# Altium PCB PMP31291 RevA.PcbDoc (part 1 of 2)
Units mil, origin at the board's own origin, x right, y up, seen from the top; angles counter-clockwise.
Board outline 2106.3 x 1624.03 mil, 4 copper layers (Top Layer, Layer 2, Layer 3, Bottom Layer), stack 73.2 mil thick; 65 components, 32 nets, 159 pads, 133 vias.
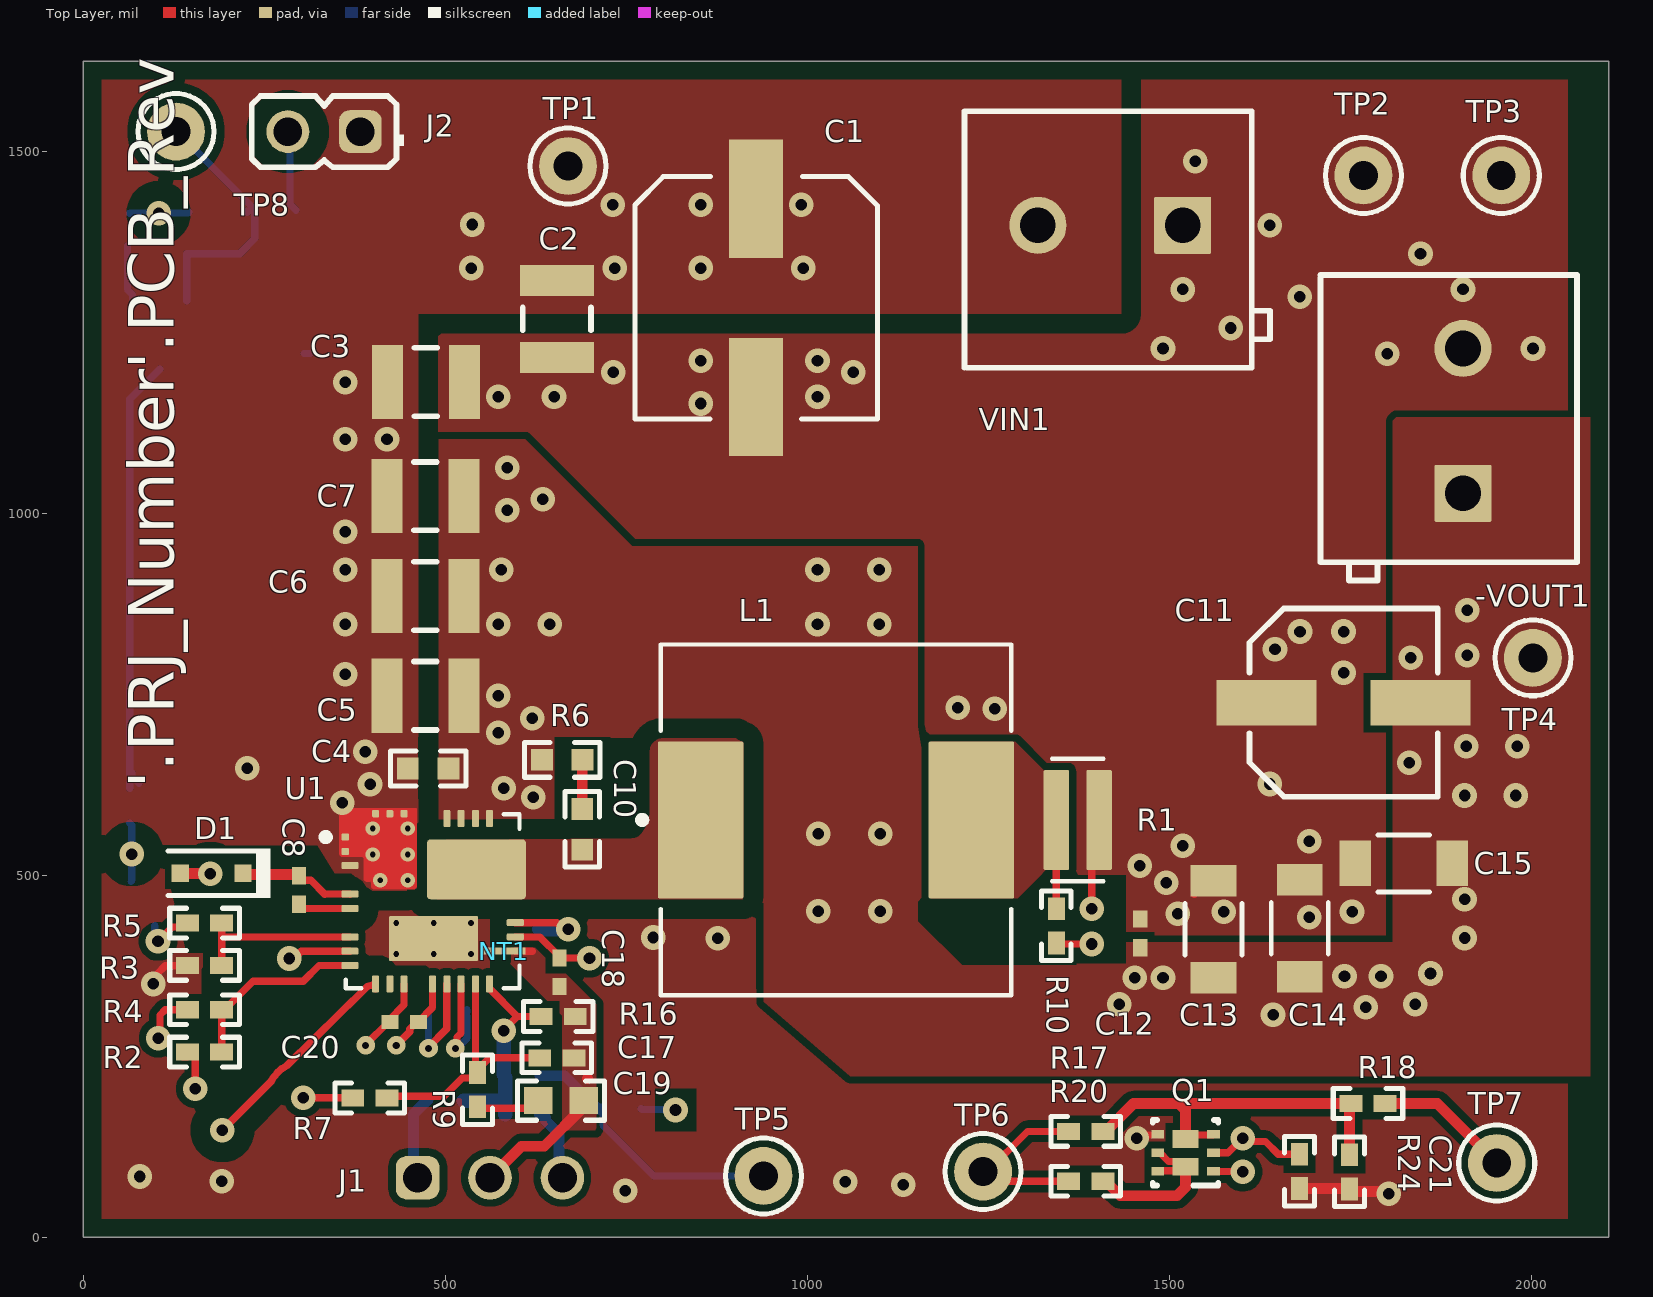
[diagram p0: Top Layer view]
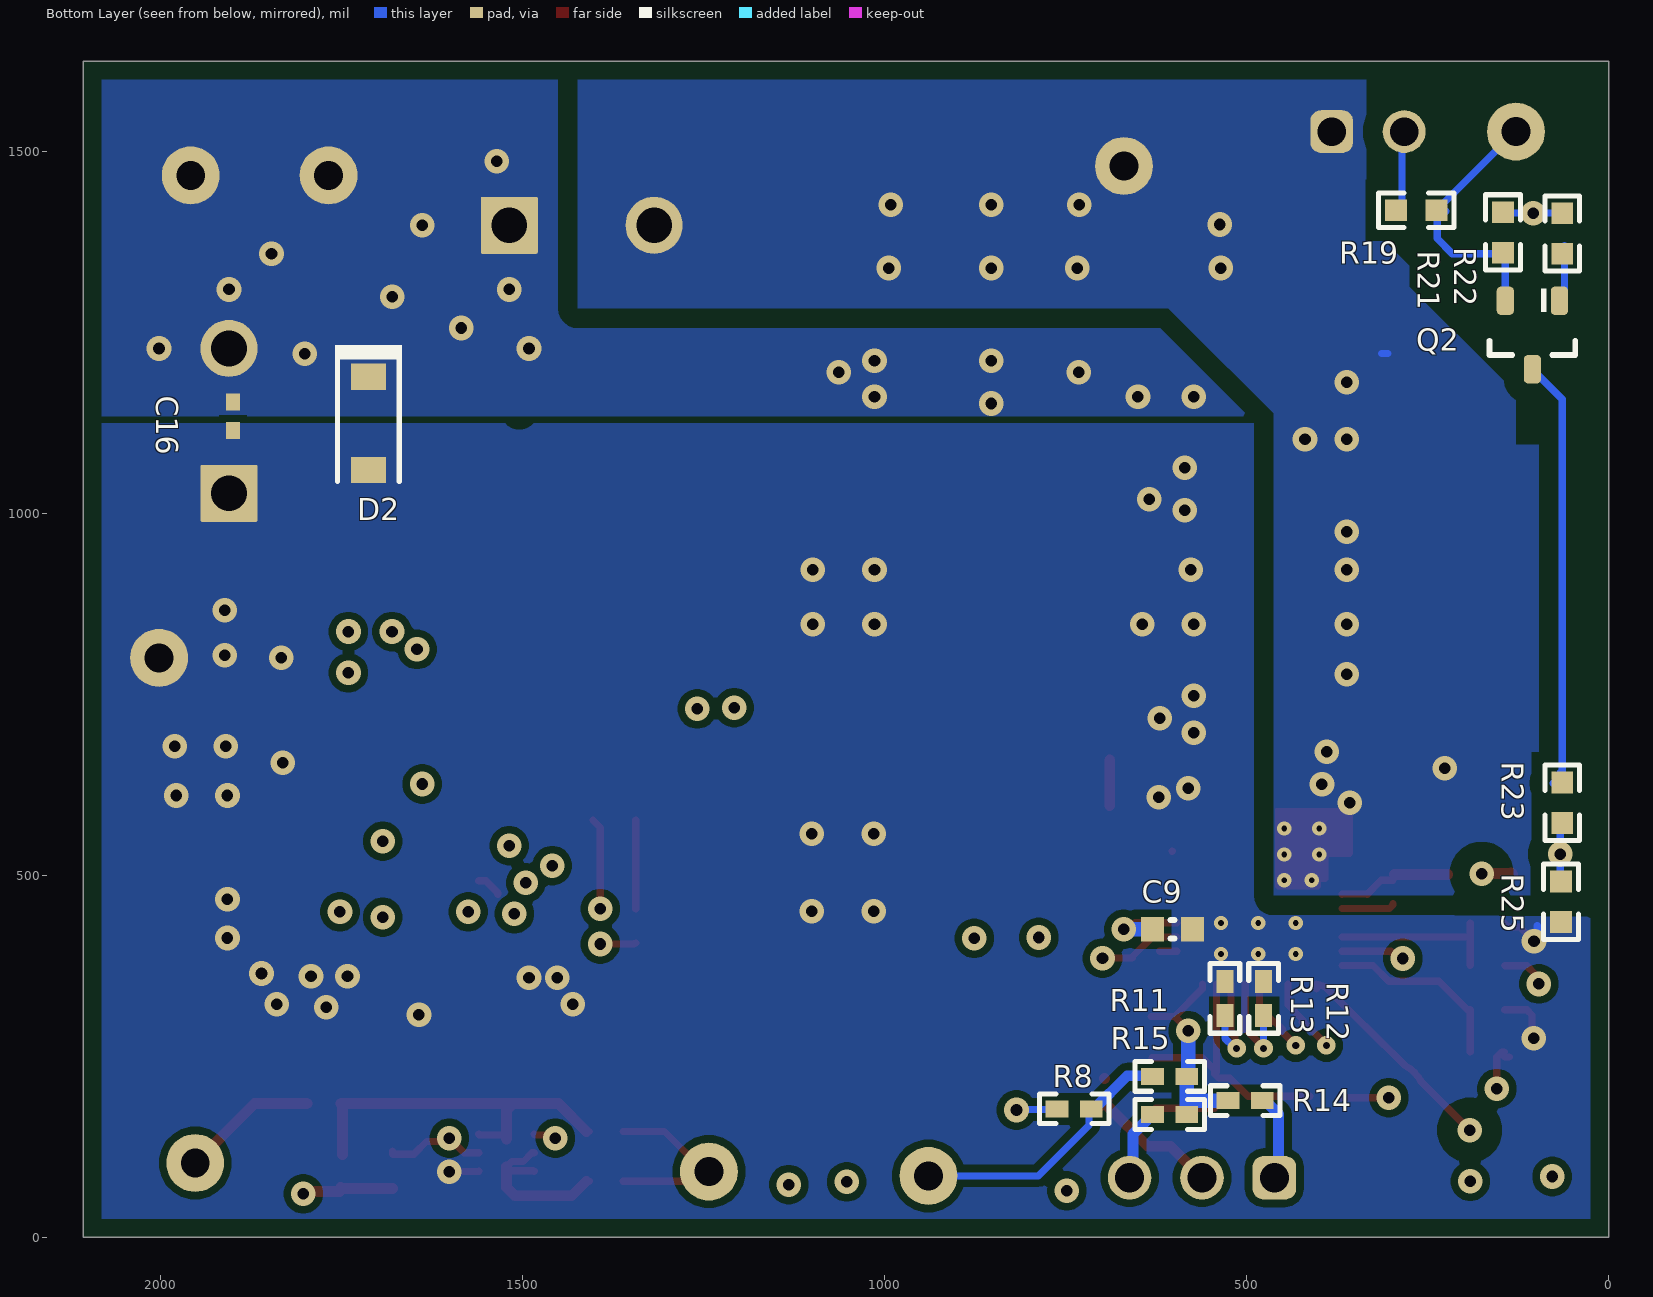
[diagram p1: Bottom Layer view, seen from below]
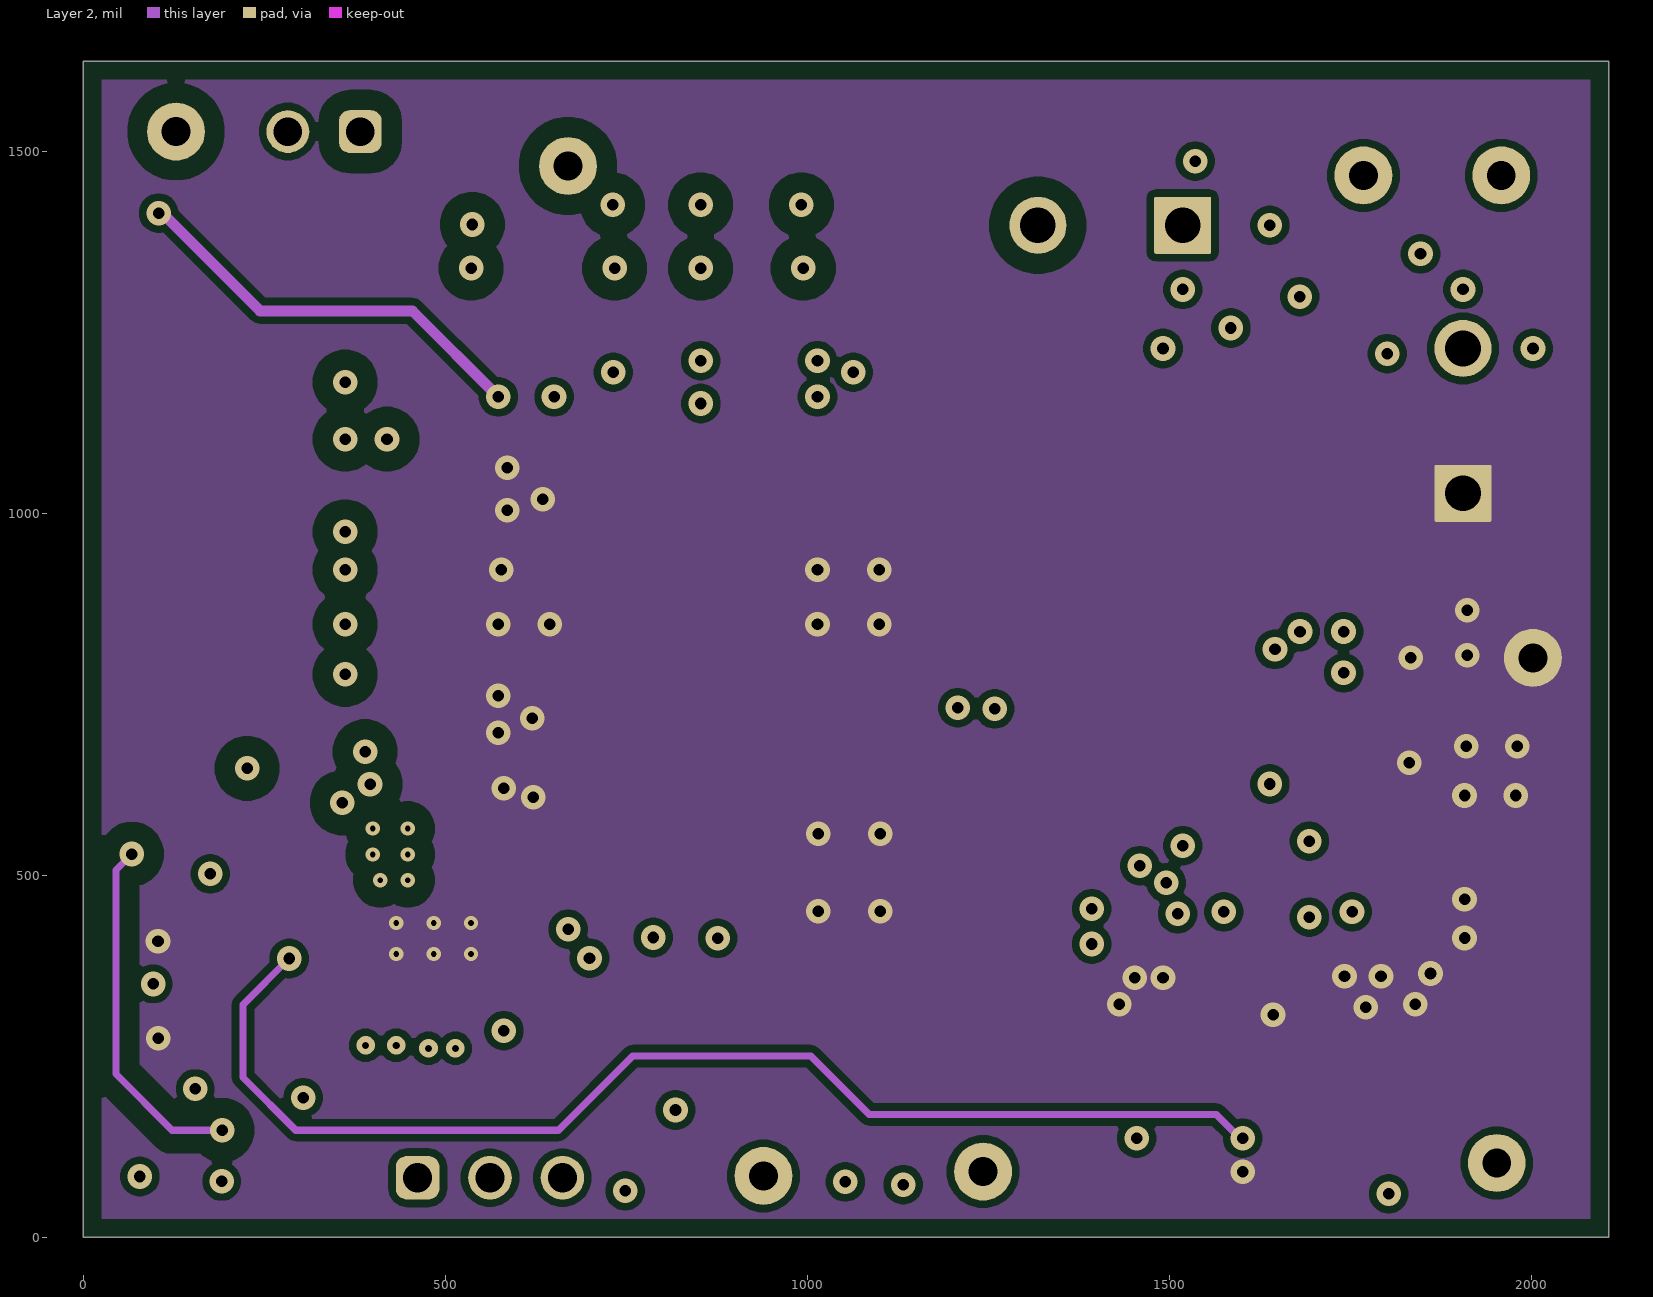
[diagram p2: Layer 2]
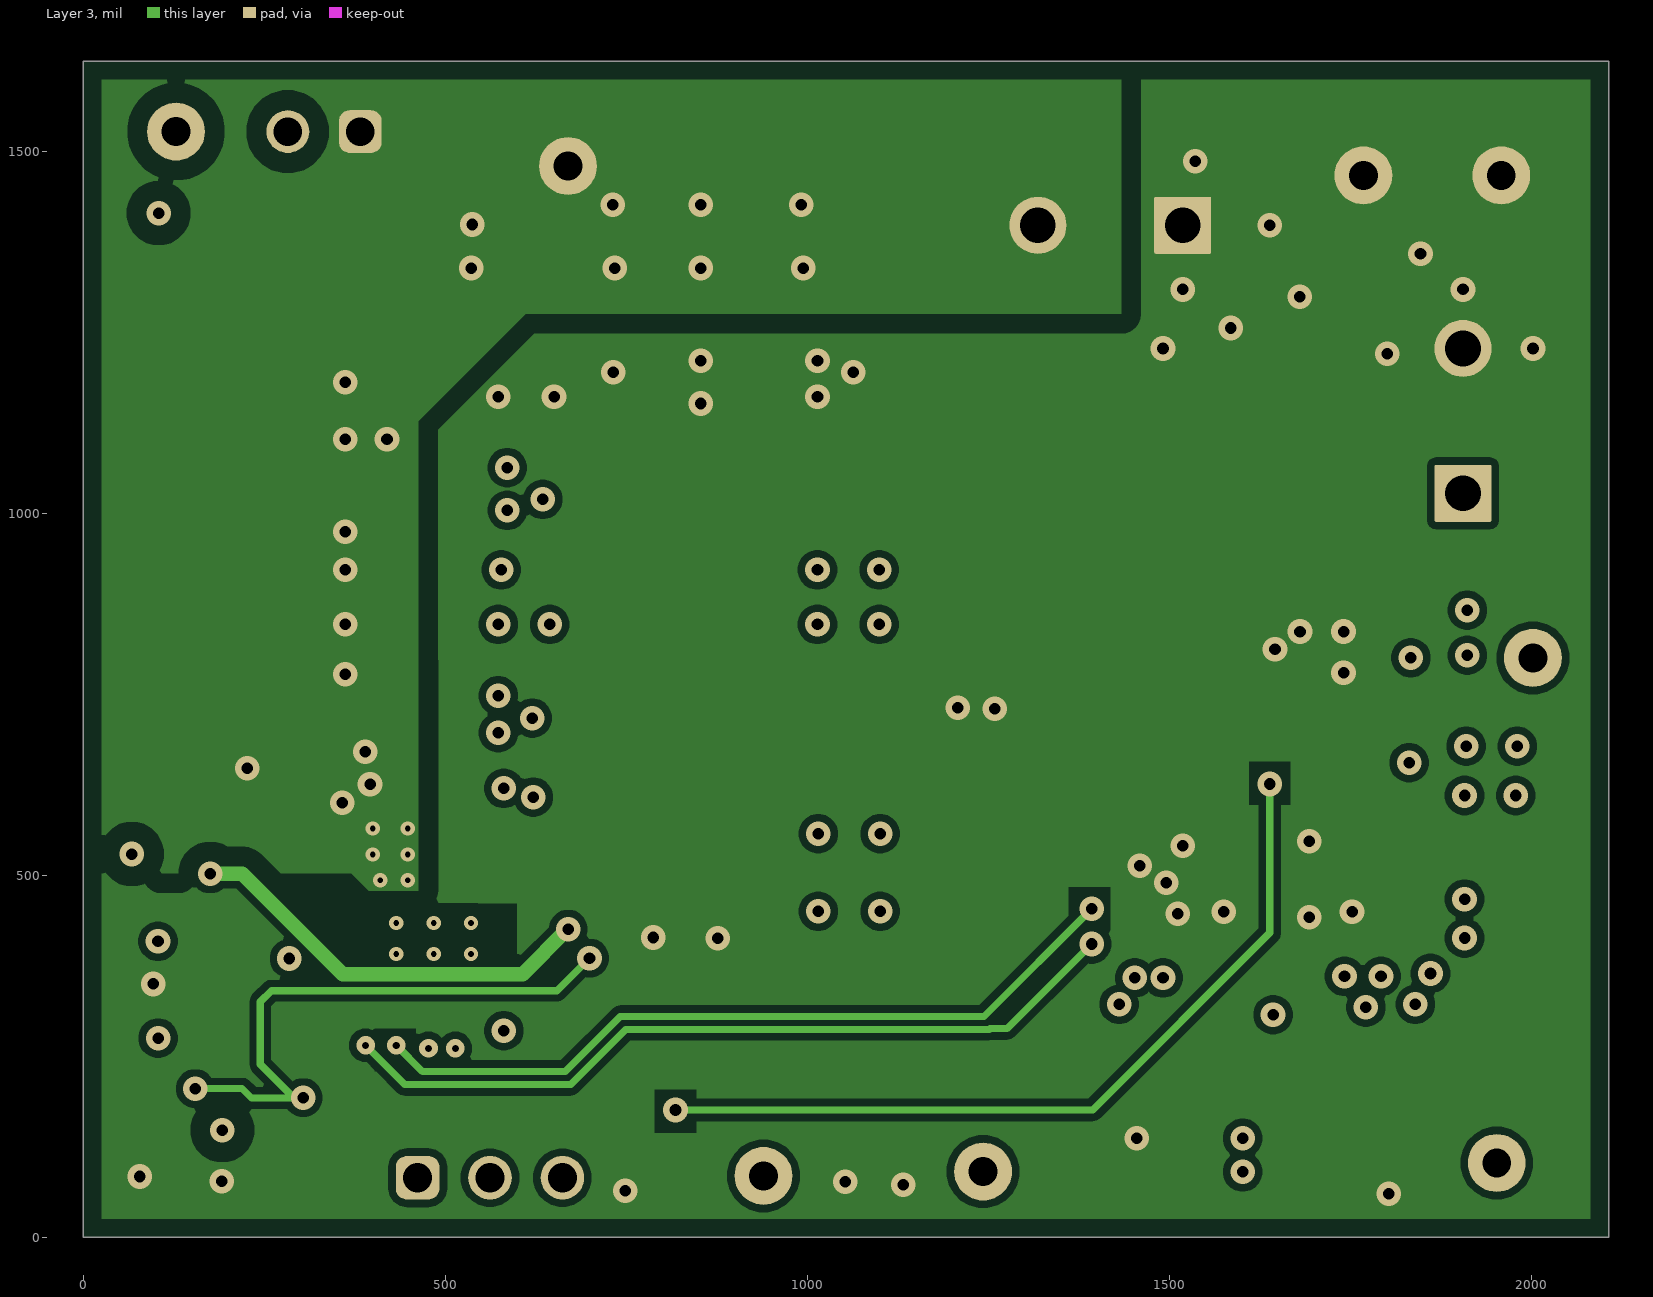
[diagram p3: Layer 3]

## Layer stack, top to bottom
Top Solder: solder mask 0.4, Solder Resist, Dk 3.5
Top Layer: signal copper 2.8
Dielectric 1: prepreg 2.8, PP-006, Dk 4.1
Layer 2: signal copper 1.4
Dielectric1: dielectric 59.2, FR-4 High Tg, Dk 4.8
Layer 3: signal copper 1.4
Dielectric 2: prepreg 2.8, PP-006, Dk 4.1
Bottom Layer: signal copper 2.8
Bottom Solder: solder mask 0.4, Solder Resist, Dk 3.5

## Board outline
0,0 0,1624.02 2106.3,1624.02 2106.3,-0.01

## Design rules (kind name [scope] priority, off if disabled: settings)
AcuteAngle [All] p1: minimum=4.50000000000000E+0001 checktracksonly=FALSE
AssemblyTestPointUsage [All] p1: valid=2
BoardOutlineClearance BoardOutlineClearance_MountingHoles [OnCopper and InComponentClass('Mounting Holes')] p1: gap=39.37 ignorepadtopadclearanceinfootprint=FALSE
BoardOutlineClearance BoardOutlineClearance_Poly [OnCopper and IsPoly] p2: gap=25 ignorepadtopadclearanceinfootprint=FALSE
BoardOutlineClearance [OnCopper and Not InComponentClass('Logo') and not InComponentClass('FiducialMark') and not InRegion(1000,500,4000,800) and not InPoly] p3: gap=40 ignorepadtopadclearanceinfootprint=FALSE
Clearance Clearance_Keepouts [((IsTrack Or IsArc) And Not InPoly) And IsFree and IsKeepOut vs ((IsTrack Or IsArc) And Not InPoly) And IsFree and IsKeepOut] p1: gap=0 ignorepadtopadclearanceinfootprint=FALSE
Clearance Clearance_VIN [InNet('VIN') vs (Not InComponent('U1')) And (Not InNet('NetC8_1'))] p2: gap=27.56 ignorepadtopadclearanceinfootprint=TRUE
Clearance Clearance_VIN_1 [InNet('VIN') vs (Not InComponent('U1')) And (InNet('NetC8_1'))] p3: gap=19.68 ignorepadtopadclearanceinfootprint=TRUE
Clearance Clearance_VIN_2 [InNet('NetJ3_2')] p4: gap=27.56 ignorepadtopadclearanceinfootprint=TRUE
Clearance Clearance_VIN_3 [InNet('NetQ2_2')] p5: gap=27.56 ignorepadtopadclearanceinfootprint=TRUE
Clearance Clearance_EN2 [InNet('NetQ2_3') vs Not InComponent('U1')] p6: gap=27.56 ignorepadtopadclearanceinfootprint=TRUE
Clearance Clearance_EN_1 [InNet('EN') vs Not InComponent('U1')] p7: gap=27.56 ignorepadtopadclearanceinfootprint=TRUE
Clearance Clearance_SW [InNet('SW') vs (Not InComponent('U1')) And (Not InNet('VCC')) And (Not InNet('NetC10_2'))] p8: gap=27.56 ignorepadtopadclearanceinfootprint=TRUE
Clearance Clearance_SW1 [InNet('SW1') vs (Not InComponent('U1')) And (Not InNet('NetC8_1'))] p9: gap=27.56 ignorepadtopadclearanceinfootprint=TRUE
Clearance Clearance_Poly [InPolygon] p10: gap=10 ignorepadtopadclearanceinfootprint=TRUE
Clearance Clearance_FiducialMark [IsKeepOut and InComponentClass('FiducialMark') vs IsPad and InComponentClass('FiducialMark')] p11: gap=0 ignorepadtopadclearanceinfootprint=FALSE
Clearance [All] p12: gap=7.87 ignorepadtopadclearanceinfootprint=TRUE
Clearance Clearance_1 [InNet('VIN') And OnLayer('Top Layer') vs InNet('GND')] p13: gap=19.68 ignorepadtopadclearanceinfootprint=TRUE
ComponentClearance ComponentClearance_MountingHoles_FiducialMarks [InComponentClass('Mounting Holes') vs InComponentClass('FiducialMark')] p1: gap=50 collisioncheckmode=3 verticalgap=10 showdistances=FALSE
ComponentClearance ComponentClearance_Shunt [InComponentClass('Header') vs InComponentClass('Shunt')] p2: gap=0 collisioncheckmode=3 verticalgap=0 showdistances=FALSE
ComponentClearance ComponentClearance_Logo [InComponentClass('Logo')] p3: gap=30 collisioncheckmode=3 verticalgap=10 showdistances=FALSE
ComponentClearance ComponentClearance_ScrewToNut [(HasFootprint('NY PMS 440 0025 PH')) vs (HasFootprint('Keystone_1902C'))] p4: gap=5 collisioncheckmode=3 verticalgap=10 showdistances=FALSE
ComponentClearance ComponentClearance_MountingHoles [InComponentClass('Mounting Holes')] p5: gap=100 collisioncheckmode=3 verticalgap=100000 showdistances=FALSE
ComponentClearance ComponentClearance_SmallPassives [HasFootprint('0201*') or HasFootprint('0402*') or HasFootprint('0508') or HasFootprint('0603*') or HasFootprint('0612') or HasFootprint('0805*') or HasFootprint('0815*') or HasFootprint('0830*') or HasFootprint('1206*') or HasFootprint('1210*') or HasFootprint('1808*') or HasFootprint('1812*') or HasFootprint('1825*') or HasFootprint('2010*') or HasFootprint('2220*') or HasFootprint('2225*') or HasFootprint('2512*') or HasFootprint('2728*') or HasFootprint('3518*') vs HasFootprint('0201*') or HasFootprint('0402*') or HasFootprint('0508') or HasFootprint('0603*') or HasFootprint('0612') or HasFootprint('0805*') or HasFootprint('0815*') or HasFootprint('0830*') or HasFootprint('1206*') or HasFootprint('1210*') or HasFootprint('1808*') or HasFootprint('1812*') or HasFootprint('1825*') or HasFootprint('2010*') or HasFootprint('2220*') or HasFootprint('2225*') or HasFootprint('2512*') or HasFootprint('2728*') or HasFootprint('3518*')] p6: gap=14.96 collisioncheckmode=3 verticalgap=10 showdistances=FALSE
ComponentClearance ComponentClearance_THtoSMT [IsThruComponent vs IsSMTComponent] p7: gap=30 collisioncheckmode=3 verticalgap=30 showdistances=FALSE
ComponentClearance ComponentClearance_THtoTH [IsThruComponent vs IsThruComponent] p8: gap=20 collisioncheckmode=3 verticalgap=30 showdistances=FALSE
ComponentClearance [All] p9: gap=20 collisioncheckmode=3 verticalgap=10 showdistances=FALSE
ComponentClearance ComponentClearance_NetTie [(HasFootprint('Net-Tie_10mil') OR HasFootprint('Net-Tie_10milWide_30milLong'))] p10: gap=0 collisioncheckmode=3 verticalgap=0 showdistances=FALSE
DiffPairsRouting [All] p1: maxlimit=100 minlimit=10 mostfreqgap=10 toplayer_minwidth=15 toplayer_maxwidth=15 toplayer_prefwidth=15 midlayer1_minwidth=15 midlayer1_maxwidth=15 midlayer1_prefwidth=15 midlayer2_minwidth=15 midlayer2_maxwidth=15 midlayer2_prefwidth=15 bottomlayer_minwidth=15 bottomlayer_maxwidth=15 bottomlayer_prefwidth=15 maxuncoupledlength=1000
FabricationTestPointUsage TestPointUsage [All] p1: valid=2 allowmultiple=FALSE
FabricationTestpoint Testpoint [All] p1: side=3 testpointundercomponent=TRUE minsize=40 maxsize=100 preferedsize=60 minholesize=0 maxholesize=40 preferedholesize=32 testpointgrid=1 allowsidetop=TRUE allowsidebottom=TRUE usegrid=TRUE gridtolerance=0.01
FanoutControl Fanout_LCC [IsLCC] p1: bgadir=Out bgaviamode=Centered fanoutstyle=Auto fanoutdirection=Alternating viagrid=1 // Fanout_LCC (Default Rule)
FanoutControl Fanout_BGA [IsBGA] p2: bgadir=Out bgaviamode=Centered fanoutstyle=Auto fanoutdirection=Alternating viagrid=1 // Fanout_BGA (Default Rule)
FanoutControl Fanout_Default [All] p4: bgadir=Out bgaviamode=Centered fanoutstyle=Auto fanoutdirection=Alternating viagrid=1 // Fanout_Default (Default Rule)
FanoutControl Fanout_Small [(CompPinCount < 5)] p5: bgadir=Out bgaviamode=Centered fanoutstyle=Auto fanoutdirection=OutThenIn viagrid=1 // Fanout_Small (Default Rule)
HoleSize [All] p1: absolutevalues=TRUE maxlimit=251 minlimit=7.87 maxpercent=80.000 minpercent=20.000
MinimumAnnularRing MinimumAnnularRing_ThermalPadVias [IsVia and InAnyComponent] p1: minimumring=5.91
MinimumAnnularRing [All] p2: minimumring=7.87
MinimumSolderMaskSliver MinimumSolderMaskSliver_Logo [InComponentClass('Logo') vs InComponentClass('Logo')] p1: minsoldermaskwidth=0.7
MinimumSolderMaskSliver [All] p2: minsoldermaskwidth=3.94
PlaneConnect [All] p1: planeconnectstyle=Relief reliefexpansion=10 reliefentries=4 reliefconductorwidth=10 reliefairgap=10
PolygonConnect [All] p1: connectstyle=Direct reliefconductorwidth=10 reliefentries=4 polygonreliefangle="90 Angle" airgapwidth=10
RoutingLayers [All] p1: top layer_v5=TRUE mid layer 1_v5=FALSE mid layer 2_v5=FALSE bottom layer_v5=TRUE
RoutingVias ThermalPadVias [IsVia and InAnyComponent] p1: holewidth=7.87 width=19.68 viastyle="Through Hole" minholewidth=7.87 minwidth=19.68 maxholewidth=12.99 maxwidth=23.62
RoutingVias [All] p2: holewidth=16 width=34 viastyle="Through Hole" minholewidth=7.87 minwidth=24 maxholewidth=40 maxwidth=65
SilkToSilkClearance SilkToSilkClearance_Pb-FreeLogo [(HasFootprint('Pb-Free_Overlay_Medium') OR HasFootprint('Pb-Free_Overlay_Small')) vs (HasFootprint('Pb-Free_Overlay_Medium') OR HasFootprint('Pb-Free_Overlay_Small'))] p1: silktosilkclearance=0
SilkToSilkClearance [All] p2: silktosilkclearance=3.94
SilkToSolderMaskClearance SilkToComponentPadClearance [(IsPad or IsFill or IsRegion) and InAnycomponent] p1: minsilkscreentomaskgap=5 clearancetoexposedcopper=TRUE
SilkToSolderMaskClearance "Silk to Solder Mask Opening" [All] p2: minsilkscreentomaskgap=3.94 clearancetoexposedcopper=FALSE
SolderMaskExpansion [All] p1: expansion=1.97 istentingtop=FALSE
UnRoutedNet [All] p1: checkbadconnections=TRUE
Width [All] p1: maxlimit=100 minlimit=6 preferedwidth=10 checkconnectedcopper=TRUE
14 further rules are at their usual default settings.

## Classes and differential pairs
component class Header: J1 J2

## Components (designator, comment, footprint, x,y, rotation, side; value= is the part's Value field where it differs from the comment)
-VOUT1 "ED120/2DS" On-Shore_ED120_2DS 1905.2,1127.55 r90 top
C1 "63SXV39M" SXV_E12 929.06,1297.46 r270 top value=39uF
C2 "GCM32DC72A475KE02L" 1210_220L 653.9,1268.29 r270 top value=4.7uF
C3 "GCM32DC72A475KE02L" 1210_220L 473.09,1181.1 r0 top value=4.7uF
C4 "GCJ188R72A104KA01D" 0603_HV 476.12,647.64 r0 top value=0.1uF
C5 "GCM32DC72A475KE02L" 1210_220L 472.44,748.03 r0 top value=4.7uF
C6 "GCM32DC72A475KE02L" 1210_220L 472.44,885.83 r0 top value=4.7uF
C7 "GCM32DC72A475KE02L" 1210_220L 472.44,1023.62 r0 top value=4.7uF
C8 "GRM155R71E104KE14D" 0402L 297.83,479.71 r270 top value=0.1uF
C9 "GRM188Z71A475ME15D" 0603L 602.31,425.59 r180 bottom value=4.7uF
C10 "GRM1885C2A101JA01D" 0603_HV 689.04,563.48 r90 top value=100pF
C11 "16SVPG270MX" SM_RADIAL_6.3AMM 1740.24,738.19 r0 top value=270uF
C12 "GRM155R71E104KE14D" 0402L 1459.57,419.73 r90 top value=0.1uF
C13 "GRM31CR71E106KA12L" 1206_180 1560.59,425.59 r270 top value=10uF
C14 "GRM31CR71E106KA12L" 1206_180 1679.79,426.94 r270 top value=10uF
C15 "GRM31CR71E106KA12L" 1206_180 1823.37,516.51 r0 top value=10uF
C16 "GRM155R71E104KE14D" 0402L 1899.61,1133.86 r90 bottom value=0.1uF
C17 "885012205044" 0402 653.9,247.92 r0 top value=1000pF
C18 "GRM155R71E104KE14D" 0402L 657.51,366.12 r90 top value=0.1uF
C19 "GRM188R71E474KA12D" 0603 659.45,188.93 r0 top value=0.47uF
C20 "GCM1555C1H330JA16D" 0402L 442.91,297.52 r180 top value=33pF
C21 "CL05B222JB5NNNC" 0402 1748.41,90.42 r270 top value=2200pF
D1 "BAT46WJ,115" SOD-323F 177.17,502.87 r180 top value=100V
D2 "BAT54T1G" SOD-123 1712.6,1123.99 r270 bottom value=30V
J1 "TSW-103-08-G-S" Samtec_TSW-103-08-x-S 561.56,82.37 r0 top
J2 "961102-6804-AR" 3M_961102-68 332.45,1527.06 r180 top
L1 "MSS1210H-103MED" FP-MSS1210H-103MED_SMT2_12MM0_12MM0-MFG 1039.37,576.51 r0 top value=10uH
NT1 "Net-Tie" Net-Tie_10milWide_30milLong 580.71,395.37 r0 top net-tie
Q1 "CSD87502Q2" DQK0006B 1522.04,116.85 r180 top value=30V
Q2 "BSS63" SOT-23 105.34,1246.14 r270 bottom value="100 V"
R1 "RLM-1632W-4F-R005-FNH" FP-RLM-1632W-4F-R005-FNH_0612-MFG 1373.17,576.41 r0 top value=5m
R2 "MCR01MZPJ000" 0402 167.32,255.91 r180 top value=0
R3 "MCR01MZPJ000" 0402 167.32,375.59 r180 top value=0
R4 "MCR01MZPJ000" 0402 167.32,314.34 r0 top value=0
R5 "MCR01MZPJ000" 0402 167.32,434.02 r0 top value=0
R6 "CRCW06032R00FKEA" 0603_HV 661.39,659.45 r180 top value=2.00
R7 "RC1005F104CS" 0402 395.51,192.48 r180 top value=100k
R8 "RC0402FR-0749R9L" 0402 738.19,177.49 r0 bottom value=49.9
R9 "CRCW04021K96FKED" 0402 544.29,203.93 r90 top value=1.96k
R10 "RC0402FR-0749R9L" 0402 1343.64,430.32 r270 top value=49.9
R11 "RC1005F104CS" 0402 606.25,222.35 r0 bottom value=100k
R12 "CRCW040229K4FKED" 0402 476.5,329.94 r270 bottom value=29.4k
R13 "CRCW040266K5FKED" 0402 529.94,329.94 r270 bottom value=66.5k
R14 "CRCW040220K0FKED" 0402 501.97,188.93 r0 bottom value=20.0k
R15 "CRCW040226K7FKED" 0402 606.25,169.7 r180 bottom value=26.7k
R16 "CRCW040213K0FKED" 0402 655.56,305.12 r180 top value=13.0k
R17 "RC1005F104CS" 0402 1384.24,146.38 r180 top value=100k
R18 "RC0402FR-0749R9L" 0402 1774,184.92 r180 top value=49.9
R19 "RC0603FR-071K2L" 0603_HV 265.75,1418.42 r0 bottom value=1.20k
R20 "RC1005F104CS" 0402 1384.24,77.48 r180 top value=100k
R21 "RC0603FR-07100KL" 0603_HV 145.99,1387.8 r270 bottom value=100k
R22 "M55342K12B10E0T" 0603_HV 64.03,1386.32 r270 bottom value=10.0k
R23 "RC0603FR-07100KL" 0603_HV 63.98,600.17 r90 bottom value=100k
R24 "RC1005F104CS" 0402 1679.36,91.26 r90 top value=100k
R25 "RC0603FR-07100KL" 0603_HV 65.73,463.54 r90 bottom value=100k
TP1 "5000" Keystone5000 669.29,1479.48 r0 top
TP2 "5001" Keystone5001 1767.64,1466.54 r0 top
TP3 "5001" Keystone5001 1958.03,1466.54 r0 top
TP4 "5000" Keystone5000 2001.79,800.34 r0 top
TP5 "5004" Keystone5004 939.23,84.95 r90 top
TP6 "5004" Keystone5004 1242.45,90.84 r90 top
TP7 "5004" Keystone5004 1951.79,102.72 r90 top
TP8 "5004" Keystone5004 127.95,1527.06 r90 top
U1 "LM70880RRXRQ1" RRX0029B-MFG 482.28,464.17 r0 top
VIN1 "ED120/2DS" On-Shore_ED120_2DS 1418.14,1397.64 r180 top

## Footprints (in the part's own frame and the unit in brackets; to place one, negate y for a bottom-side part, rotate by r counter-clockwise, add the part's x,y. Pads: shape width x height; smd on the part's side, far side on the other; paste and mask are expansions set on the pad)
3M_961102-68 [mm] "Header, 2.54mm, 2x1, TH"
  rrect50% 1.5x1.5 hole 1: 1(-1.27,0)
  round 1.5 hole 1: 2(1.27,0)
  silkscreen extent -2.8,-1.25 2.54,1.25, body extent -2.54,-1.25 2.54,1.25, height 9.3
0402 [mm] "0402 from SM-752 data"
  rect 0.8x0.6 smd: 1(-0.6,0) 2(0.6,0)
  silkscreen extent -1.22,-0.52 1.22,0.52, body extent -0.55,-0.3 0.55,0.3, height 0.6
0402L [mm] "0402 from SM-752 data"
  rect 0.6x0.5 smd: 1(-0.5,0) 2(0.5,0)
  body extent -0.55,-0.3 0.55,0.3, height 0.6
0603 [mm] "0603 from SM-752 data"
  rect 1x0.95 smd: 1(-0.8,0) 2(0.8,0)
  silkscreen extent -1.52,-0.69 1.52,0.69, body extent -0.87,-0.47 0.87,0.47, height 1
0603_HV [mil] "Ernesto recommended land pattern.  26 mil between pads."
  rect 30x30 smd: 1(-28,0) 2(28,0)
  silkscreen extent -52,-24 52,24, body extent -34,-19 34,19, height 39
0603L [mm] "0603 from SM-752 data"
  rect 0.8x0.85 smd: 1(-0.7,0) 2(0.7,0)
  silkscreen extent -0.07,-0.33 0.07,0.33, body extent -0.87,-0.47 0.87,0.47, height 1
1206_180 [mm] "1206_180"
  rect 1.1x1.6 smd: 1(-1.7,0) 2(1.7,0)
  silkscreen extent -0.9,-1 0.9,1, body extent -1.75,-0.95 1.75,0.95, height 1.8
1210_220L [mm] "1210"
  rect 1.1x2.6 smd: 1(-1.35,0) 2(1.35,0)
  silkscreen extent -0.4,-1.2 0.4,1.2, body extent -1.7,-1.35 1.7,1.35, height 2.2
DQK0006B [mm] "TI"
  rect 0.45x0.3 smd: 1(-0.975,0.65) 2(-0.975,0) 3(-0.975,-0.65) 4(0.975,-0.65) 5(0.975,0) 6(0.975,0.65)
  rect 0.9x0.625 smd paste-0.025: 7(0,0.488) 8(0,-0.488)
  silkscreen extent -1.15,-1.15 1.15,1.15, body extent -1.05,-1.05 1.05,1.05, height 0.8
FP-MSS1210H-103MED_SMT2_12MM0_12MM0-MFG [mm]
  rrect3% 3x5.5 smd paste+0 mask+0: 1(-4.75,0) 2(4.75,0)
  silkscreen extent -6.92,-6.15 6.15,6.15, body extent -6.35,-6.25 6.35,6.25, height 0.25
FP-RLM-1632W-4F-R005-FNH_0612-MFG [mm]
  rrect11% 0.9x3.5 smd paste+0 mask+0: 1(-0.75,0) 2(0.75,0)
  silkscreen extent -0.9,-2.15 0.9,2.15, body extent -1.3,-1.85 1.3,1.85, height 0.25
Keystone5000 [mil] "For Keystone 500x miniature loop terminals"
  round 80 hole 40: 1(0,0)
  silkscreen extent -52,-52 52,52, body extent -49,-49 49,49, height 182
Keystone5001 [mil] "For Keystone 500x miniature loop terminals"
  round 80 hole 40: 1(0,0)
  silkscreen extent -52,-52 52,52, body extent -49,-49 49,49, height 182
Keystone5004 [mil] "For Keystone 500x miniature loop terminals"
  round 80 hole 40: 1(0,0)
  silkscreen extent -52,-52 52,52, body extent -49,-49 49,49, height 182
Net-Tie_10milWide_30milLong [mil] "10mil net tie, no solder mask opening, no solder paste"
  rect 30x10 smd paste-5 mask-5: 1(-15,0) 2(15,0)
On-Shore_ED120_2DS [mm] "ONSHORE"
  rrect5% 2x2 hole 1.25: 1(-2.54,0)
  round 2 hole 1.25: 2(2.54,0)
  silkscreen extent -5.6,-4 5.12,5, body extent -5.78,-4 5.08,5, height 13
RRX0029B-MFG [mm]
  rrect40% 0.267x0.25 smd paste+0 mask-1000: 1(-3.066,2.25) 2(-3.066,1.75)
  rrect40% 0.6x0.25 smd paste+0 mask+0: 3(-2.9,1.25) 4(-2.9,0.25) 5(-2.9,-0.25) 6(-2.9,-1.25) 7(-2.9,-1.75) 8(-2.9,-2.25) 17(2.9,-1.75) 18(2.9,-1.25) 19(2.9,-0.75)
  rrect40% 0.25x0.6 smd paste+0 mask+0: 9(-2,-2.9) 10(-1.5,-2.9) 11(-1,-2.9) 12(0,-2.9) 13(0.5,-2.9) 14(1,-2.9) 15(1.5,-2.9) 16(2,-2.9) 23(2,2.9) 24(1.5,2.9) 25(1,2.9) 26(0.5,2.9)
  rrect40% 0.293x0.25 smd paste+0 mask-1000: 20(3.054,0.75) 21(3.054,1.25) 22(3.054,1.75)
  rrect40% 0.25x0.258 smd paste+0 mask-1000: 27(-1,3.071) 28(-1.5,3.071) 29(-2,3.071)
  rrect6% 3.125x1.584 smd paste-1000 mask+0: 30(0.037,-1.308)
  rrect11% 3.465x2.1 smd paste-1000 mask-1000: ""(1.537,1.12)
  Top Layer region: -3.27,3.22 -3.263,3.245 -3.245,3.263 -3.22,3.27 -3.22,3.27 -0.605,3.27 -0.586,3.266 -0.57,3.255 -0.559,3.239 -0.555,3.22 -0.555,3.22 -0.555,0.534 -0.564,0.488 -0.59,0.449 -0.629,0.423 -0.675,0.414 -0.675,0.414 -2.034,0.414 -2.08,0.423 -2.119,0.449 -2.145,0.488 -2.154,0.534 -2.154,0.534 -2.154,0.641 -2.158,0.66 -2.169,0.676 -2.185,0.687 -2.204,0.691 -2.204,0.691 -2.3,0.691 -2.346,0.7 -2.385,0.726 -2.411,0.765 -2.42,0.811 -2.42,0.811 -2.42,1.505 -2.427,1.53 -2.445,1.548 -2.47,1.555 -2.47,1.555 -3.15,1.555 -3.196,1.564 -3.235,1.59 -3.261,1.629 -3.27,1.675 -3.27,1.675
  silkscreen extent -3.87,-3.05 3.05,3.05, body extent -3.37,-3.3 3.37,3.37, height 0.25
Samtec_TSW-103-08-x-S [mm] "Header, 2.54mm, 3x1, TH"
  rrect50% 1.53x1.53 hole 1.02: 1(-2.54,0)
  round 1.53 hole 1.02: 2(0,0) 3(2.54,0)
  body extent -3.94,-1.27 3.81,1.27, height 8.38
SM_RADIAL_6.3AMM [mm] "Nichicon 6.3x5.8"
  rect 3.5x1.6 smd: 1(-2.7,0) 2(2.7,0)
  silkscreen extent -3.3,-3.29 3.3,3.31, body extent -3.5,-3.3 3.5,3.3, height 6.11
SOD-123 [mm] "On Semi recommended land pattern"
  rect 0.915x1.22 smd: 1(-1.637,0) 2(1.637,0)
  silkscreen extent -2.74,-1.17 2.03,1.17, body extent -1.93,-0.9 1.93,0.9, height 1.35
SOD-323F [mm] "NXP recommended land pattern"
  rect 0.6x0.6 smd paste-0.05: 1(-1.1,0) 2(1.1,0)
  silkscreen extent -2.06,-0.86 1.53,0.86, body extent -1.35,-0.67 1.35,0.68, height 0.79
SOT-23 [mm] "SOT23, 3-Leads, Body 2.9x1.3mm, Pitch 0.95mm, Lead Span 2.5mm, IPC Medium Density"
  rrect50% 1x0.6 smd: 1(-1.2,0.95) 2(-1.2,-0.95) 3(1.2,0)
  silkscreen extent -1.63,-1.5 0.7,1.5, body extent -1.16,-1.45 1.21,1.45, height 1
SXV_E12 [mm] "OS-CON  8x10"
  rect 4.15x1.9 smd: 1(-3.475,0) 2(3.475,0)
  silkscreen extent -4.25,-4.25 4.25,4.25, body extent -4.25,-4.25 4.25,4.25, height 12

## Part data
-VOUT1 VIN1: library part CMP-0074910-1, "Terminal Block, 5.08 mm, 2x1, Brass, TH", Color=Blue, Current_A=15A, Manufacturer="On-Shore Technology", Supplier Part Number 1=ED1609-ND, Voltage_V=300V
C1: library part CMP-0012145-3, "CAP, Aluminum Polymer, 39 uF, 63 V, +/- 20%, 0.025 ohm, 8.0x11.9mm SMD", Cap_Case=8.0x11.9, Manufacturer=Panasonic, Tolerance_%=20%, Value1="0.025 ohm", Value2=63V, ValueDisplayed=39uF
C2 C3 C5 C6: library part CMP-0082268-1, "CAP, CERM, 4.7 µF, 100 V,+/- 10%, X7S, AEC-Q200 Grade 1, 1210", Cap_Case=1210, Manufacturer=MuRata, Supplier Part Number 1=490-14484-1-ND, TempCo=X7S, Tolerance_%=10%, Value1="0.001 ohm", Value2=100V, ValueDisplayed=4.7µF
C4: library part CMP-0064935-4, "CAP, CERM, 0.1 uF, 100 V,+/- 10%, X7R, AEC-Q200 Grade 1, 0603", Cap_Case=0603, Manufacturer=MuRata, Supplier Part Number 1=490-13420-1-ND, TempCo=X7R, Tolerance_%=10%, Value1=Unknown, Value2=100V, ValueDisplayed=0.1uF
C7: library part CMP-0082268-1, "CAP, CERM, 4.7 µF, 100 V,+/- 10%, X7S, AEC-Q200 Grade 1, 1210", Cap_Case=1210, Manufacturer=MuRata, Supplier Part Number 1=490-14484-1-ND, TempCo=X7S, Tolerance_%=10%, Value1="0.001 ohm", Value2=100V, ValueDisplayed=DNP
C8 C12 C16 C18: library part CMP-0006659-2, "CAP, CERM, 0.1 uF, 25 V, +/- 10%, X7R, 0402", Cap_Case=0402, Manufacturer=MuRata, Supplier Part Number 1=490-10698-1-ND, TempCo=X7R, Tolerance_%=10%, Value1=Unknown, Value2=25V, ValueDisplayed=0.1uF
C9: library part CMP-0007498-4, "CAP, CERM, 4.7 uF, 10 V, +/- 20%, X7R, 0603", Cap_Case=0603, Manufacturer=MuRata, TempCo=X7R, Tolerance_%=20%, Value1=Unknown, Value2=10V, ValueDisplayed=4.7uF
C10: library part CMP-0007237-4, "CAP, CERM, 100 pF, 100 V, +/- 5%, C0G/NP0, 0603", Cap_Case=0603, Manufacturer=MuRata, Supplier Part Number 1=490-1351-1-ND, TempCo=C0G/NP0, Tolerance_%=5%, Value1=Unknown, Value2=100V, ValueDisplayed=DNP
C11: library part CMP-0012070-3, "CAP, Aluminum Polymer, 270 uF, 16 V, +/- 20%, 10 mohm, 6.3x7.9 SMD", Manufacturer=Panasonic, Value2=16V, ValueDisplayed=270uF
C13 C14: library part CMP-0008965-2, "CAP, CERM, 10 uF, 25 V, +/- 10%, X7R, 1206", Cap_Case=2220, Manufacturer=MuRata, Supplier Part Number 1=81-GRM31CR71E106KA12, TempCo=X7R, Tolerance_%=10%, Value1=Unknown, Value2=25V, ValueDisplayed=10uF
C15: library part CMP-0008965-2, "CAP, CERM, 10 uF, 25 V, +/- 10%, X7R, 1206", Cap_Case=2220, Manufacturer=MuRata, Supplier Part Number 1=81-GRM31CR71E106KA12, TempCo=X7R, Tolerance_%=10%, Value1=Unknown, Value2=25V, ValueDisplayed=DNP
C17: library part CMP-0006229-2, "CAP, CERM, 1000 pF, 25 V, +/- 10%, X7R, 0402", Cap_Case=0402, Manufacturer="Wurth Elektronik", Supplier Part Number 1=710-885012205044, TempCo=X7R, Tolerance_%=10%, Value1=Unknown, Value2=25V, ValueDisplayed=1000pF
C19: library part CMP-0007424-4, "CAP, CERM, 0.47 uF, 25 V, +/- 10%, X7R, 0603", Cap_Case=0603, Manufacturer=MuRata, Supplier Part Number 1=490-3291-1-ND, TempCo=X7R, Tolerance_%=10%, Value1=Unknown, Value2=25V, ValueDisplayed=0.47uF
C20: library part CMP-0860833-1, "CAP, CERM, 33 pF, 50 V,+/- 5%, C0G/NP0, AEC-Q200 Grade 1, 0402", Cap_Case=0402, Manufacturer=MuRata, TempCo=C0G/NP0, Tolerance_%=5%, Value2=50V, ValueDisplayed=33pF
C21: library part CMP-0006344-2, "CAP, CERM, 2200 pF, 50 V, +/- 5%, X7R, 0402", Cap_Case=0402, Manufacturer="Samsung Electro-Mechanics", Supplier Part Number 1=1276-1532-1-ND, TempCo=X7R, Tolerance_%=5%, Value1=Unknown, Value2=50V, ValueDisplayed=2200pF
D1: library part CMP-0076946-2, "Diode, Schottky, 100 V, 0.25 A, SOD-323F", Manufacturer=Nexperia, Value1=0.25A, Value2=0.85V
D2: library part CMP-0028457-2, "Diode, Schottky, 30 V, 0.2 A, SOD-123", Manufacturer="ON Semiconductor", Value1=0.2A, Value2=0.8V
J1: library part CMP-0079327-1, "Header, 2.54mm, 3x1, Gold, TH", Color=Black, Manufacturer=Samtec, Supplier Part Number 1=SAM1038-03-ND
J2: library part CMP-0075355-2, "Header, 2.54mm, 2x1, Gold, TH", Color=Black, Current_A=2A, Manufacturer=3M, Supplier Part Number 1=3M155862-ND
L1: library part CMP-0094344-1, "Shielded Power Inductor 10uH ±20% 0.013 Ohms 9.1A", Manufacturer=Coilcraft, Operating Temperature Range=to, Self Resonant Frequency=18MHz, Test Frequency=100kHz, Tolerance_%=20%
NT1: library part CMP-0078142-6, "Single point connection between nets.", Manufacturer=N/A
Q1: library part CMP-0000608-1, "MOSFET, 2-CH, N-CH, 30 V, 5 A, DQK0006B (WSON-6)", Alternate Manufacturer=None, Manufacturer="Texas Instruments", Supplier Part Number 1=CSD87502Q2-ND, Value1=0.04, Value2="2.2 nC"
Q2: library part CMP-0000366-2, "Transistor, PNP, 100 V, 0.2 A, SOT-23", Manufacturer="Fairchild Semiconductor", Supplier Part Number 1=BSS63CT-ND, Value1="0.2 A"
R1: library part CMP-0091128-1, "Res 0.005 Ohm 1% 1/2W 1206", Digikey Part Number=2037-RLM-1632W-4F-R005-FNHCT-ND, Manufacturer=Cyntec, Operating Temperature Range="-55°C to +170°C", Power_W=500mW, TempCo=100ppm/°C, Tolerance_%=1%
R2 R3 R4: library part CMP-0027002-2, "RES, 0, 5%, 0.063 W, 0402", Manufacturer=Rohm, Power_W=63mW, Supplier Part Number 1=RHM0.0JCT-ND, TempCo="500 ppm/C", Tolerance_%=5%, Value2=0.063W, Value_Code=0000, ValueDisplayed=0
R5: library part CMP-0027002-2, "RES, 0, 5%, 0.063 W, 0402", Manufacturer=Rohm, Power_W=63mW, Supplier Part Number 1=RHM0.0JCT-ND, TempCo="500 ppm/C", Tolerance_%=5%, Value2=0.063W, Value_Code=0000, ValueDisplayed=DNP
R6: library part CMP-0022302-4, "RES, 2.00, 1%, 0.1 W, AEC-Q200 Grade 0, 0603", Manufacturer=Vishay-Dale, Power_W=100mW, Supplier Part Number 1=541-2.00HHCT-ND, TempCo="100 ppm/C", Tolerance_%=1%, Value2=0.1W, Value_Code=2R00, ValueDisplayed=DNP
R7: library part CMP-0026745-1, "RES, 100 k, 1%, 0.063 W, 0402", Manufacturer="Samsung Electro-Mechanics", Power_W=63mW, Supplier Part Number 1=1276-3432-1-ND, TempCo="100 ppm/C", Tolerance_%=1%, Value2=0.063W, Value_Code=100k, ValueDisplayed=DNP
R8 R10 R18: library part CMP-0026738-1, "RES, 49.9, 1%, 0.063 W, 0402", Manufacturer="Yageo America", Power_W=63mW, Supplier Part Number 1=311-49.9LRCT-ND, TempCo="100 ppm/C", Tolerance_%=1%, Value2=0.063W, Value_Code=49R9, ValueDisplayed=49.9
R9: library part CMP-0026099-2, "RES, 1.96 k, 1%, 0.063 W, AEC-Q200 Grade 0, 0402", Manufacturer=Vishay-Dale, Power_W=63mW, Supplier Part Number 1=541-1.96KLCT-ND, TempCo="100 ppm/C", Tolerance_%=1%, Value2=0.063W, Value_Code=1k96, ValueDisplayed=1.96k
R11 R17 R20 R24: library part CMP-0026745-1, "RES, 100 k, 1%, 0.063 W, 0402", Manufacturer="Samsung Electro-Mechanics", Power_W=63mW, Supplier Part Number 1=1276-3432-1-ND, TempCo="100 ppm/C", Tolerance_%=1%, Value2=0.063W, Value_Code=100k
R12: library part CMP-0026225-2, "RES, 29.4 k, 1%, 0.063 W, AEC-Q200 Grade 0, 0402", Manufacturer=Vishay-Dale, Power_W=63mW, Supplier Part Number 1=541-29.4KLCT-ND, TempCo="100 ppm/C", Tolerance_%=1%, Value2=0.063W, Value_Code=29k4, ValueDisplayed=29.4k
R13: library part CMP-0026502-2, "RES, 66.5 k, 1%, 0.063 W, AEC-Q200 Grade 0, 0402", Manufacturer=Vishay-Dale, Power_W=63mW, Supplier Part Number 1=541-66.5KLCT-ND, TempCo="100 ppm/C", Tolerance_%=1%, Value2=0.063W, Value_Code=66k5, ValueDisplayed=66.5k
R14: library part CMP-0026162-2, "RES, 20.0 k, 1%, 0.063 W, AEC-Q200 Grade 0, 0402", Manufacturer=Vishay-Dale, Power_W=63mW, Supplier Part Number 1=541-20.0KLCT-ND, TempCo="100 ppm/C", Tolerance_%=1%, Value2=0.063W, Value_Code=20k0, ValueDisplayed=20.0k
R15: library part CMP-0026208-2, "RES, 26.7 k, 1%, 0.063 W, AEC-Q200 Grade 0, 0402", Manufacturer=Vishay-Dale, Power_W=63mW, Supplier Part Number 1=541-26.7KLCT-ND, TempCo="100 ppm/C", Tolerance_%=1%, Value2=0.063W, Value_Code=26k7, ValueDisplayed=26.7k
R16: library part CMP-0026003-3, "RES, 13.0 k, 1%, 0.063 W, AEC-Q200 Grade 0, 0402", Manufacturer=Vishay-Dale, Power_W=63mW, Supplier Part Number 1=541-13.0KLCT-ND, TempCo="100 ppm/C", Tolerance_%=1%, Value2=0.063W, Value_Code=13k0, ValueDisplayed=13.0k
R19: library part CMP-0022874-5, "RES, 1.20 k, 1%, 0.1 W, 0603", Manufacturer=Yageo, Power_W=100mW, Supplier Part Number 1=311-1.20KHRCT-ND, TempCo="100 ppm/C", Tolerance_%=1%, Value2=0.1W, Value_Code=1k20, ValueDisplayed=1.20k
R21 R23 R25: library part CMP-0022735-5, "RES, 100 k, 1%, 0.1 W, 0603", Manufacturer=Yageo, Power_W=100mW, Supplier Part Number 1=311-100KHRCT-ND, TempCo="100 ppm/C", Tolerance_%=1%, Value2=0.1W, Value_Code=100k
R22: library part CMP-0080488-1, "RES, 10.0 k, 1%, 0.1 W, 0603", Manufacturer="TT Electronics/IRC", Power_W=100mW, TempCo="100 ppm/C", Tolerance_%=1%, Value2=0.1W, Value_Code=10k0, ValueDisplayed=10.0k
TP1 TP4: library part CMP-0055137-2, "Test Point, Miniature, Red, TH", Color=Red, Manufacturer="Keystone Electronics", Supplier Part Number 1=36-5000-ND
TP2 TP3: library part CMP-0055138-2, "Test Point, Miniature, Black, TH", Color=Black, Manufacturer="Keystone Electronics", Supplier Part Number 1=36-5001-ND
TP5 TP6 TP7 TP8: library part CMP-0055141-2, "Test Point, Miniature, Yellow, TH", Color=Yellow, Manufacturer="Keystone Electronics", Supplier Part Number 1=36-5004-ND
U1: library part CMP-0096026-3, "80-V, 8-A Synchronous DC/DC Buck Converter With Ultra-Low IQ, VQFN29", Manufacturer="Texas Instruments", Max Supply Voltage=80V, Min Supply Voltage=4.5V, Operating Temperature Range="-40°C to +150°C", Output Voltage=0.8-55V, Switching Frequency=0.2-2.2MHz

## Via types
v1: diameter 34, hole 16, Top Layer to Bottom Layer, tented both sides, 117 vias
v2: diameter 19.68, hole 7.87, Top Layer to Bottom Layer, 12 vias
v3: diameter 25.75, hole 10, Top Layer to Bottom Layer, tented both sides, 4 vias

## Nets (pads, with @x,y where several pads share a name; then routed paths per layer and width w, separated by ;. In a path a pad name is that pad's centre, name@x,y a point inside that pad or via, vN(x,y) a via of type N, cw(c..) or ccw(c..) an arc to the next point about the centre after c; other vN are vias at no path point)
-VOUT: -VOUT1.1 C4.2 C5.2 C6.2 C7.2 C9.2 C11.2 C12.1 C13.2 C14.2 C15.2 C16.1 D2.2 NT1.1 Q1.1 R4.1 R5.1 R6.2 R12.1 R13.1 R25.1 TP4.1 U1.23 U1.24 U1.25 U1.26 U1.30 | length 189.2
  Top Layer w10: v1(103.12,408.86) 123.07,428.8 138.49,428.8 R5.1@143.7,434.02 ; v1(103.17,275.24) 105.86,277.94 105.86,307.24 112.95,314.34 R4.1@143.7,314.34 ; Q1.1@1560.42,91.26 1560.84,90.84 1600.36,90.84 v1(1600.78,90.42)
  Bottom Layer w10: 98.53,430.52 98.53,413.45 v1(103.12,408.86)
  other v1: 1642.88,307.48 1771.07,317.9 1430.27,321.87 1839.46,321.87 1451.87,358.34 1490.88,358.34 1741.56,360.46 1791.92,360.46 1860.3,364.43 1907.32,413.39 1014.95,450.27 1100.2,450.27 1907.32,467.21 1014.95,557.54 1100.2,557.54 621.31,608.03 1907.32,610.24 1978.06,610.24 580.71,620.08 1830.71,655.55 1909.45,678.35 1980.19,678.35 573.16,697 619.92,717.16 573.16,748.03 1833.27,800.34 1911.29,803.89 573.16,846.46 643.9,846.46 1013.78,846.46 1099.02,846.46 1911.29,866.14 577.04,921.82 1013.78,921.82 1099.02,921.82 585.47,1003.94 634.45,1019.15 585.38,1062.99
  other v2: 432.09,391.34 483.74,391.34 535.43,391.34 432.09,434.02 483.74,434.02 535.43,434.02
AGND: C17.2 C18.1 C19.2 J1.2 NT1.2 R16.1 U1.17 | length 220.9
  Top Layer w10: U1.17@596.46,395.28 619.92,395.28 ; C19.2@689.96,188.93 C19.2@690.94,188.93 C19.2@704.57,175.3
  Top Layer w15: J1.2@555.71,76.52 605.05,125.86 636.53,125.86 C19.2@689.96,179.29 ; 696.16,219.47 696.42,219.21
CONFIG: R12.2 U1.13 | length 144.9
  Top Layer w10: v3(476.61,260.96) 476.61,262.58 501.97,287.94 U1.13@501.97,350
  Bottom Layer w10: R12.2@476.5,306.32 476.56,306.26 476.56,261.02 v3(476.61,260.96)
EN: R23.1 R25.2 U1.9 | length 881.8
  Top Layer w10: v1@62.37,524.77 v1(66.96,529.36) ; v1(191.84,148.1) 259.46,215.72 cw(c303.49,192.98) 280.46,236.86 281.46,237.85 391.96,346.41 U1.9@403.54,350 403.54,343.27 U1.9@403.46,343.19
  Layer 2 w10: v1(66.96,529.36) 45,507.4 45,225.62 122.52,148.1 v1(191.84,148.1)
  Bottom Layer w10: R23.1@63.98,572.17 66.96,569.19 v1(66.96,529.36) 66.96,492.77 R25.2@65.73,491.54
FBA: R11.1 R14.2 R15.2 R16.2 U1.16 | length 298.9
  Top Layer w10: U1.16@561.02,350 561.02,343.27 599.17,305.12 ; v1(580.71,285.43) 580.71,286.65 599.17,305.12 ; R16.2@631.94,305.12 599.17,305.12
  Bottom Layer w10: 576.42,188.93 582.63,195.14 ; R11.1@580.71,224.27 R11.1@582.63,222.35
  Bottom Layer w20: R14.2@525.59,188.93 576.42,188.93 ; R11.1@580.71,224.27 v1(580.71,285.43) v1@584.5,285.43 ; R15.2@582.63,169.7 582.63,195.14 R11.1@582.63,220.57
GND: -VOUT1.2 C1.2 C2.2 C3.2 C11.1 C12.2 C13.1 C14.1 C15.1 C16.2 C20.1 C21.2 D2.1 Q1.4 R1.2 R3.2 R8.2 R21.1 R22.1 R24.1 TP2.1 TP3.1 U1.12 VIN1.1 | length 3404.6
  Top Layer w10: v1(96.25,350) 100.85,354.59 100.85,362.94 112.95,375.04 143.15,375.04 R3.2@143.7,375.59 ; v3(432.09,265.16) 450.82,283.89 450.82,287.71 460.63,297.52 C20.1@462.6,297.52 482.28,317.91 U1.12@482.28,350 ; v1(1392.46,453.94) 1392.46,566.19 R1.2@1402.69,576.41 ; v1(1454.4,137) 1458.94,141.53 1482.74,141.53 Q1.4@1483.65,142.44 ; C13.1@1534.1,473.6 1534.1,475.86 1550.75,492.51 C13.1@1560.59,492.51 ; C21.2@1747.58,67.64 C21.2@1748.41,66.8 C21.2@1750.8,69.19
  Top Layer w15: R24.1@1679.36,67.64 C21.2@1747.58,67.64 ; C21.2@1750.8,69.19 1750.8,65.39 1752.72,63.47 1799.22,63.47 v1(1802.55,60.14)
  Layer 2 w10: v1@103.94,1411.43 v1(103.94,1414.44)
  Layer 2 w15: v1@100.69,1422.75 243.91,1279.53 454.28,1279.53 v1(573.16,1160.65)
  Layer 3 w10: v3(432.09,265.16) 468.15,229.09 665.51,229.09 741.54,305.12 1243.64,305.12 v1(1392.46,453.94) ; v1(817.7,175.9) 1393.85,175.9 1638.45,420.51 v1(1638.45,626.07)
  Bottom Layer w10: R22.1@64.03,1414.32 64.15,1414.44 v1(103.94,1414.44) 144.64,1414.44 R21.1@145.99,1415.8 ; R8.2@770.45,177.67 771.42,176.7 816.9,176.7 v1(817.7,175.9)
  other v1: 748.13,64.37 1131.99,72.95 191.05,77.47 1052.3,76.59 78.11,84.05 875.98,413.05 786.82,414.17 1692.91,442.16 1511.1,446.81 1574.8,449.58 1751.97,449.58 1495.31,489.48 1458.94,513.39 1518.14,540.97 1692.91,547.12 1258.55,729.79 1207.55,731.47 1740.24,779.68 1645.51,812.01 1680.06,836.61 1740.24,836.61 852.8,1151.57 650,1160.65 1013.78,1160.65 731.73,1194.73 1062.99,1194.73 852.36,1210.63 1013.78,1210.63 1800.55,1220.47 1490.88,1227.55 2001.79,1227.55 1584.65,1255.83 1679.79,1299.21 1518.14,1309.06 1905.2,1309.06 1846.54,1358.27 1638.45,1397.64 1535.43,1486.22
NetC8_1: C8.1 D1.1 U1.4 | length 157
  Top Layer w10: D1.1@220.47,502.87 D1.1@222.21,501.14 ; C8.1@296.09,501.14 C8.1@297.83,499.4 ; C8.1@297.83,493.04 314.3,493.04 333.32,474.02 368.03,474.09 U1.4@368.11,474.02
  Top Layer w15: D1.1@222.21,501.14 C8.1@296.09,501.14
